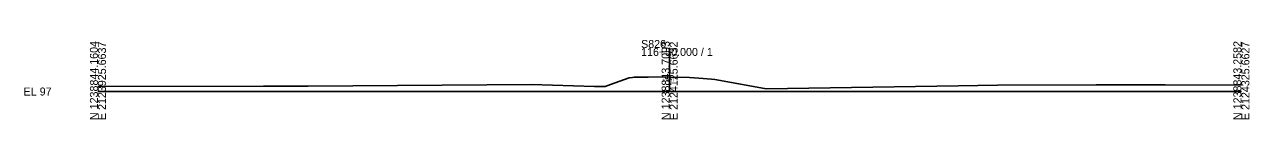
# Model space of a CAD drawing. Extents: x 2119282 to 2119710, y 1215030 to 1220057.
# Drawn here: x 2119281.9 to 2119710.4, y 1215030.1 to 1215057.9 of the extents above; entities that cross this region are included whole.
import ezdxf

# ---------------------------------------------------------------- set-up
doc = ezdxf.new("R2010")
doc.units = 0
for name, color, linetype in [('XS_CELL', 7, 'Continuous'), ('XS_X_GROUND', 7, 'Continuous'), ('XS_X_GROUND_TX', 7, 'Continuous')]:
    doc.layers.add(name, color=color, linetype=linetype)

msp = doc.modelspace()

# ---------------------------------------------------------------- linework, layer by layer
at = {"layer": 'XS_CELL'}
for p, q in [((2119507.6, 1215039.8), (2119507.6, 1215055.06)), ((2119307.6, 1215039.8), (2119507.6, 1215039.8)), ((2119507.6, 1215039.8), (2119707.6, 1215039.8))]:
    msp.add_line(p, q, dxfattribs=at)
at = {"layer": 'XS_X_GROUND'}
for p, q in [((2119486.94, 1215042.24), (2119493.46, 1215044.62)), ((2119493.46, 1215044.62), (2119494.59, 1215044.72)), ((2119494.59, 1215044.72), (2119495.22, 1215044.79)), ((2119495.22, 1215044.79), (2119500.05, 1215044.85)), ((2119500.05, 1215044.85), (2119506.91, 1215044.89)), ((2119506.91, 1215044.89), (2119507.6, 1215044.87)), ((2119507.6, 1215044.87), (2119514.54, 1215044.66)), ((2119514.54, 1215044.66), (2119517.85, 1215044.53)), ((2119517.85, 1215044.53), (2119522.26, 1215044.14)), ((2119307.6, 1215041.54), (2119308.23, 1215041.54)), ((2119308.23, 1215041.54), (2119365.5, 1215041.64)), ((2119365.5, 1215041.64), (2119381.11, 1215041.66)), ((2119381.11, 1215041.66), (2119459.31, 1215042.29)), ((2119459.31, 1215042.29), (2119481.35, 1215041.61)), ((2119481.35, 1215041.61), (2119485, 1215041.6)), ((2119485, 1215041.6), (2119486.94, 1215042.24)), ((2119522.26, 1215044.14), (2119523.44, 1215044.02)), ((2119523.44, 1215044.02), (2119527.94, 1215043.24)), ((2119527.94, 1215043.24), (2119541.37, 1215040.71)), ((2119541.37, 1215040.71), (2119608.57, 1215041.83)), ((2119608.57, 1215041.83), (2119622.32, 1215042.08)), ((2119622.32, 1215042.08), (2119656.85, 1215042.09)), ((2119656.85, 1215042.09), (2119676.58, 1215042.11)), ((2119676.58, 1215042.11), (2119680.93, 1215042.11)), ((2119680.93, 1215042.11), (2119707.6, 1215042))]:
    msp.add_line(p, q, dxfattribs=at)

# ---------------------------------------------------------------- texts
at = {"layer": 'XS_CELL'}
for s, p in [('N 1238844.1604', (2119307.6, 1215029.8)), ('E 2123925.6637', (2119310.4, 1215029.8)), ('N 1238843.7093', (2119507.6, 1215029.8)), ('E 2124125.6632', (2119510.4, 1215029.8)), ('N 1238843.2582', (2119707.6, 1215029.8)), ('E 2124325.6627', (2119710.4, 1215029.8))]:
    msp.add_text(s, height=2.8, rotation=90, dxfattribs=at).set_placement(p)
for s, p in [('S826', (2119497.6, 1215055.06)), ('116+50.000 / 1', (2119497.6, 1215052.26)), ('EL 97', (2119281.6, 1215038.4))]:
    msp.add_text(s, height=2.8, dxfattribs=at).set_placement(p)
at = {"layer": 'XS_X_GROUND_TX'}
msp.add_text('102.07', height=1, dxfattribs=at).set_placement((2119505.03, 1215043.27))

doc.saveas('drawing.dxf')
